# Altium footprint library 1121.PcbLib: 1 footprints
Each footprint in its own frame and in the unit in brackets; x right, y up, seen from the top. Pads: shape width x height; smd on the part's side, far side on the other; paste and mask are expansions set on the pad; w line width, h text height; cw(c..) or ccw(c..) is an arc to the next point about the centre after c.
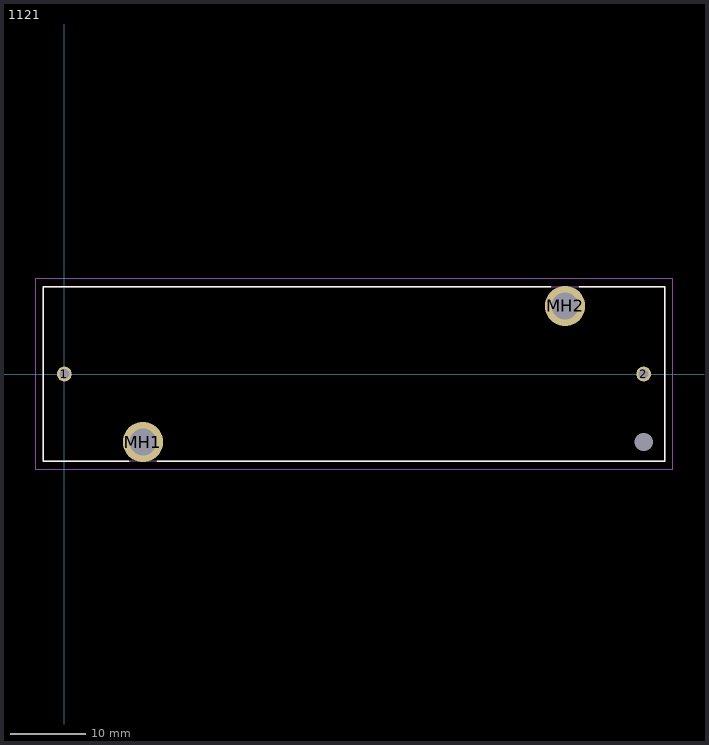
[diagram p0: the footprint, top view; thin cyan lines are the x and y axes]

## 1121 [mm]
pads (5):
  round 1.98 hole 1.32: 1(0,0) 2(76.66,0)
  round 5.325 hole 3.55: MH1(10.405,-9) MH2(66.255,9)
  round 1.195 hole 2.39 unplated: MH3(76.66,-9)
Top Overlay:
  lines w0.2: 8.53,-11.53 -2.765,-11.53 -2.765,11.53 64.33,11.53 ; 12.33,-11.53 79.425,-11.53 79.425,11.53 68.13,11.53
Mechanical 15:
  lines w0.1: -2.765,-11.53 79.425,-11.53 79.425,11.53 -2.765,11.53 -2.765,-11.53
Mechanical 20:
  lines w0.1: -3.765,-12.662 80.425,-12.662 80.425,12.662 -3.765,12.662 -3.765,-12.662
